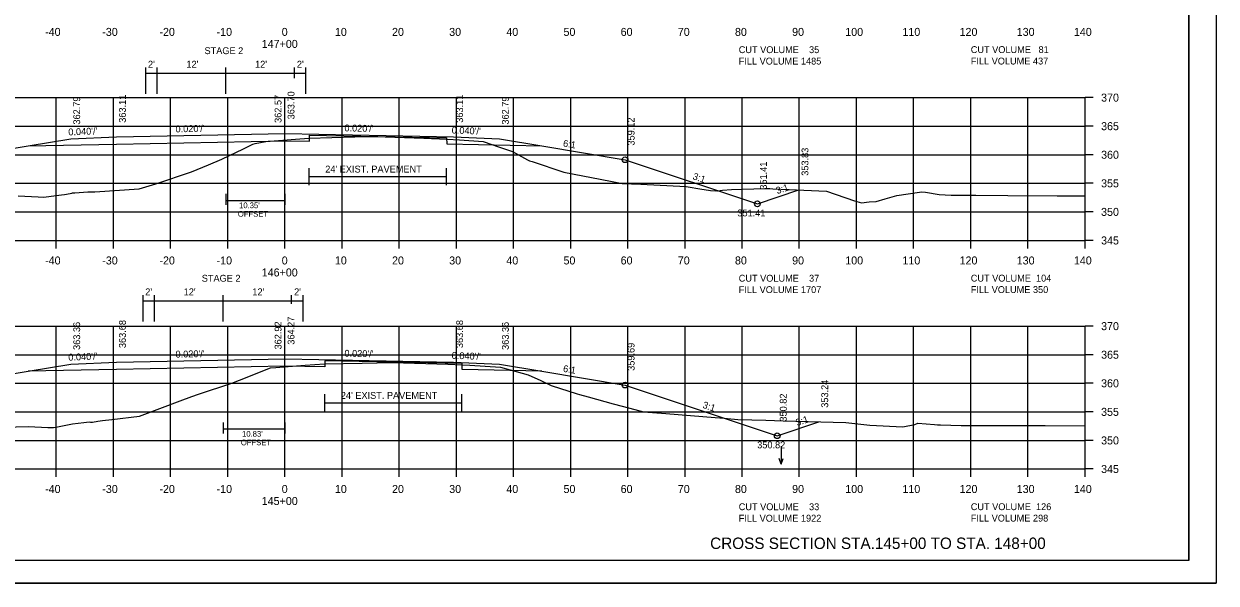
# Model space of a CAD drawing. Extents: x 1374859 to 1376773, y 382242 to 389804.
# Drawn here: x 1376088.9 to 1376297.5, y 386295.2 to 386393.1 of the extents above; entities that cross this region are included whole.
import ezdxf

# ---------------------------------------------------------------- set-up
doc = ezdxf.new("R2010")
doc.units = 0
for name, color, linetype in [('R_Axis', 7, 'Continuous'), ('R_Axis Annot', 7, 'Continuous'), ('R_Border', 7, 'Continuous'), ('R_Border Notes', 7, 'Continuous'), ('R_Draft', 7, 'Continuous'), ('R_Exist Surface', 7, 'Continuous'), ('R_Fin Surface', 7, 'Continuous'), ('R_Grid', 7, 'Continuous'), ('R_MOT', 7, 'Continuous'), ('R_No Plot', 7, 'Continuous'), ('R_Water Annot', 7, 'Continuous'), ('R_Xsect Elev', 7, 'Continuous'), ('R_Xsect Slope', 7, 'Continuous')]:
    doc.layers.add(name, color=color, linetype=linetype)

msp = doc.modelspace()

# ---------------------------------------------------------------- linework, layer by layer
at = {"layer": 'R_Axis'}
for p, q in [((1376274.57, 386355.14), (1376274.57, 386380.14)), ((1376275.97, 386380.14), (1376274.57, 386380.14)), ((1376275.97, 386375.14), (1376274.57, 386375.14)), ((1376275.97, 386370.14), (1376274.57, 386370.14)), ((1376275.97, 386365.14), (1376274.57, 386365.14)), ((1376275.97, 386360.14), (1376274.57, 386360.14)), ((1375994.57, 386355.14), (1376274.57, 386355.14)), ((1376094.57, 386353.74), (1376094.57, 386355.14)), ((1376104.57, 386353.74), (1376104.57, 386355.14)), ((1376114.57, 386353.74), (1376114.57, 386355.14)), ((1376124.57, 386353.74), (1376124.57, 386355.14)), ((1376134.57, 386353.74), (1376134.57, 386355.14)), ((1376144.57, 386353.74), (1376144.57, 386355.14)), ((1376154.57, 386353.74), (1376154.57, 386355.14)), ((1376164.57, 386353.74), (1376164.57, 386355.14)), ((1376174.57, 386353.74), (1376174.57, 386355.14)), ((1376184.57, 386353.74), (1376184.57, 386355.14)), ((1376194.57, 386353.74), (1376194.57, 386355.14)), ((1376204.57, 386353.74), (1376204.57, 386355.14)), ((1376214.57, 386353.74), (1376214.57, 386355.14)), ((1376224.57, 386353.74), (1376224.57, 386355.14)), ((1376234.57, 386353.74), (1376234.57, 386355.14)), ((1376244.57, 386353.74), (1376244.57, 386355.14)), ((1376254.57, 386353.74), (1376254.57, 386355.14)), ((1376264.57, 386353.74), (1376264.57, 386355.14)), ((1376274.57, 386353.74), (1376274.57, 386355.14)), ((1376275.97, 386355.14), (1376274.57, 386355.14)), ((1376274.57, 386315.14), (1376274.57, 386340.14)), ((1376275.97, 386340.14), (1376274.57, 386340.14)), ((1376275.97, 386335.14), (1376274.57, 386335.14)), ((1376275.97, 386330.14), (1376274.57, 386330.14)), ((1376275.97, 386325.14), (1376274.57, 386325.14)), ((1376275.97, 386320.14), (1376274.57, 386320.14)), ((1375994.57, 386315.14), (1376274.57, 386315.14)), ((1376094.57, 386313.74), (1376094.57, 386315.14)), ((1376104.57, 386313.74), (1376104.57, 386315.14)), ((1376114.57, 386313.74), (1376114.57, 386315.14)), ((1376124.57, 386313.74), (1376124.57, 386315.14)), ((1376134.57, 386313.74), (1376134.57, 386315.14)), ((1376144.57, 386313.74), (1376144.57, 386315.14)), ((1376154.57, 386313.74), (1376154.57, 386315.14)), ((1376164.57, 386313.74), (1376164.57, 386315.14)), ((1376174.57, 386313.74), (1376174.57, 386315.14)), ((1376184.57, 386313.74), (1376184.57, 386315.14)), ((1376194.57, 386313.74), (1376194.57, 386315.14)), ((1376204.57, 386313.74), (1376204.57, 386315.14)), ((1376214.57, 386313.74), (1376214.57, 386315.14)), ((1376224.57, 386313.74), (1376224.57, 386315.14)), ((1376234.57, 386313.74), (1376234.57, 386315.14)), ((1376244.57, 386313.74), (1376244.57, 386315.14)), ((1376254.57, 386313.74), (1376254.57, 386315.14)), ((1376264.57, 386313.74), (1376264.57, 386315.14)), ((1376274.57, 386313.74), (1376274.57, 386315.14)), ((1376275.97, 386315.14), (1376274.57, 386315.14))]:
    msp.add_line(p, q, dxfattribs=at)
at = {"layer": 'R_Border'}
for q in [(1376292.75, 386504.6), (1375976.57, 386299.14)]:
    msp.add_line((1376292.75, 386299.14), q, dxfattribs=at)
at = {"layer": 'R_Border Notes'}
for points in [[(1376138.75, 386367.81), (1376138.75, 386364.81)], [(1376162.76, 386367.81), (1376162.76, 386364.81)], [(1376138.75, 386366.31), (1376162.76, 386366.31)], [(1376141.48, 386328.21), (1376141.48, 386325.21)], [(1376165.48, 386328.21), (1376165.48, 386325.21)], [(1376141.48, 386326.71), (1376165.48, 386326.71)]]:
    msp.add_lwpolyline(points, dxfattribs=at)
at = {"layer": 'R_Exist Surface'}
for points in [[(1376087.89, 386362.93), (1376091.4, 386362.75), (1376092.31, 386362.7), (1376092.79, 386362.77), (1376095.49, 386363.15), (1376096.02, 386363.21), (1376096.97, 386363.37), (1376097.27, 386363.41), (1376097.42, 386363.46), (1376097.83, 386363.48), (1376100.06, 386363.63), (1376101.29, 386363.65), (1376109.09, 386364.16), (1376111.97, 386365.07), (1376118.21, 386367.14), (1376121.21, 386368.36), (1376123.51, 386369.35), (1376127.3, 386371.2), (1376128.97, 386372.02), (1376129.34, 386372.09), (1376131.24, 386372.45), (1376136.44, 386372.86), (1376138.75, 386373.03), (1376146.78, 386373.25), (1376150.42, 386373.34), (1376158.87, 386373.03), (1376162.97, 386372.87), (1376165.14, 386372.73), (1376169.24, 386372.45), (1376172.12, 386371.47), (1376174.4, 386370.68), (1376177.04, 386369.26), (1376177.38, 386369.08), (1376177.81, 386368.93), (1376183.39, 386367.07), (1376191.54, 386365.49), (1376193.58, 386365.13), (1376196.86, 386364.98), (1376204.79, 386364.59), (1376207.54, 386364.14), (1376208.7, 386363.95), (1376209.02, 386363.9), (1376209.89, 386363.84), (1376210.06, 386363.86), (1376210.14, 386363.85), (1376210.28, 386363.83), (1376211.14, 386363.93), (1376212.7, 386364.05), (1376218.54, 386364.21), (1376219.41, 386364.23), (1376219.94, 386364.2), (1376222.8, 386364.04), (1376225.36, 386363.95), (1376229.32, 386363.77), (1376234.25, 386362.09), (1376235.46, 386361.72), (1376236.8, 386361.91), (1376237.99, 386361.98), (1376239.58, 386362.43), (1376241.63, 386363.03), (1376245.57, 386363.58), (1376246.03, 386363.64), (1376246.62, 386363.59), (1376249.05, 386363.16), (1376251.13, 386363.04), (1376254.11, 386363.06), (1376255.43, 386363.08), (1376261.04, 386363.03), (1376269.69, 386362.93), (1376274.57, 386362.94)], [(1376083.22, 386322.42), (1376089.68, 386322.58), (1376093.09, 386322.42), (1376094.05, 386322.4), (1376094.47, 386322.49), (1376097.4, 386323.07), (1376099.37, 386323.27), (1376100.32, 386323.37), (1376100.55, 386323.36), (1376100.91, 386323.36), (1376101.85, 386323.52), (1376102.63, 386323.65), (1376104.29, 386323.83), (1376109.1, 386324.38), (1376116.22, 386327.06), (1376118.28, 386327.81), (1376119.45, 386328.21), (1376125.3, 386330.16), (1376126.6, 386330.67), (1376132.04, 386332.84), (1376133, 386332.92), (1376134.36, 386333.04), (1376138.09, 386333.3), (1376141.48, 386333.53), (1376148.07, 386333.68), (1376153.37, 386333.8), (1376163.07, 386333.46), (1376165.59, 386333.38), (1376166.93, 386333.31), (1376172.26, 386332.95), (1376173.99, 386332.49), (1376177.14, 386331.61), (1376179.32, 386330.65), (1376181.15, 386329.75), (1376185.72, 386328.32), (1376186.12, 386328.19), (1376187.6, 386327.77), (1376192.01, 386326.52), (1376194.9, 386325.78), (1376197.3, 386325.17), (1376201.23, 386324.85), (1376209.87, 386324.14), (1376211.4, 386324.01), (1376213.83, 386323.83), (1376218.7, 386323.67), (1376221.75, 386323.56), (1376232.73, 386323.25), (1376236.93, 386322.83), (1376242.69, 386322.51), (1376244.77, 386322.93), (1376245.33, 386323.15), (1376248.2, 386322.91), (1376248.74, 386322.87), (1376249.26, 386322.85), (1376252.89, 386322.74), (1376259.75, 386322.76), (1376264.43, 386322.76), (1376267.57, 386322.74), (1376274.57, 386322.69)]]:
    msp.add_lwpolyline(points, dxfattribs=at)
at = {"layer": 'R_Fin Surface'}
for points in [[(1376045, 386362.59), (1376050.02, 386360.91), (1376075.09, 386369.27), (1376089.65, 386371.7), (1376097.09, 386372.93), (1376105.09, 386373.25), (1376134.59, 386373.84), (1376164.09, 386373.25), (1376172.09, 386372.93), (1376179.51, 386371.7), (1376194.09, 386369.27), (1376217.23, 386361.55), (1376224.5, 386363.98)], [(1376089.65, 386371.7), (1376105.1, 386372), (1376134.58, 386372.59)], [(1376134.58, 386372.59), (1376138.85, 386372.51), (1376138.86, 386373.59), (1376162.86, 386373.11), (1376162.87, 386372.03), (1376179.51, 386371.7)], [(1376042.49, 386322.47), (1376047.74, 386320.72), (1376075.09, 386329.83), (1376089.65, 386332.26), (1376097.09, 386333.5), (1376105.09, 386333.82), (1376134.59, 386334.41), (1376164.09, 386333.82), (1376172.09, 386333.5), (1376179.51, 386332.26), (1376194.09, 386329.83), (1376220.7, 386320.96), (1376227.96, 386323.38)], [(1376134.58, 386333.16), (1376105.1, 386332.57), (1376089.65, 386332.26)], [(1376179.51, 386332.26), (1376165.59, 386332.54), (1376165.58, 386333.62), (1376141.58, 386334.1), (1376141.57, 386333.02), (1376134.58, 386333.16)]]:
    msp.add_lwpolyline(points, dxfattribs=at)
at = {"layer": 'R_Grid'}
for p, q in [((1375994.57, 386380.14), (1376274.57, 386380.14)), ((1376094.57, 386355.14), (1376094.57, 386380.14)), ((1376104.57, 386355.14), (1376104.57, 386380.14)), ((1376114.57, 386355.14), (1376114.57, 386380.14)), ((1376124.57, 386355.14), (1376124.57, 386380.14)), ((1376134.57, 386355.14), (1376134.57, 386380.14)), ((1376144.57, 386355.14), (1376144.57, 386380.14)), ((1376154.57, 386355.14), (1376154.57, 386380.14)), ((1376164.57, 386355.14), (1376164.57, 386380.14)), ((1376174.57, 386355.14), (1376174.57, 386380.14)), ((1376184.57, 386355.14), (1376184.57, 386380.14)), ((1376194.57, 386355.14), (1376194.57, 386380.14)), ((1376204.57, 386355.14), (1376204.57, 386380.14)), ((1376214.57, 386355.14), (1376214.57, 386380.14)), ((1376224.57, 386355.14), (1376224.57, 386380.14)), ((1376234.57, 386355.14), (1376234.57, 386380.14)), ((1376244.57, 386355.14), (1376244.57, 386380.14)), ((1376254.57, 386355.14), (1376254.57, 386380.14)), ((1376264.57, 386355.14), (1376264.57, 386380.14)), ((1376274.57, 386355.14), (1376274.57, 386380.14)), ((1375994.57, 386375.14), (1376274.57, 386375.14)), ((1375994.57, 386370.14), (1376274.57, 386370.14)), ((1375994.57, 386365.14), (1376274.57, 386365.14)), ((1375994.57, 386360.14), (1376274.57, 386360.14)), ((1375994.57, 386355.14), (1376274.57, 386355.14)), ((1375994.57, 386340.14), (1376274.57, 386340.14)), ((1376094.57, 386315.14), (1376094.57, 386340.14)), ((1376104.57, 386315.14), (1376104.57, 386340.14)), ((1376114.57, 386315.14), (1376114.57, 386340.14)), ((1376124.57, 386315.14), (1376124.57, 386340.14)), ((1376134.57, 386315.14), (1376134.57, 386340.14)), ((1376144.57, 386315.14), (1376144.57, 386340.14)), ((1376154.57, 386315.14), (1376154.57, 386340.14)), ((1376164.57, 386315.14), (1376164.57, 386340.14)), ((1376174.57, 386315.14), (1376174.57, 386340.14)), ((1376184.57, 386315.14), (1376184.57, 386340.14)), ((1376194.57, 386315.14), (1376194.57, 386340.14)), ((1376204.57, 386315.14), (1376204.57, 386340.14)), ((1376214.57, 386315.14), (1376214.57, 386340.14)), ((1376224.57, 386315.14), (1376224.57, 386340.14)), ((1376234.57, 386315.14), (1376234.57, 386340.14)), ((1376244.57, 386315.14), (1376244.57, 386340.14)), ((1376254.57, 386315.14), (1376254.57, 386340.14)), ((1376264.57, 386315.14), (1376264.57, 386340.14)), ((1376274.57, 386315.14), (1376274.57, 386340.14)), ((1375994.57, 386335.14), (1376274.57, 386335.14)), ((1375994.57, 386330.14), (1376274.57, 386330.14)), ((1375994.57, 386325.14), (1376274.57, 386325.14)), ((1375994.57, 386320.14), (1376274.57, 386320.14)), ((1375994.57, 386315.14), (1376274.57, 386315.14))]:
    msp.add_line(p, q, dxfattribs=at)
at = {"layer": 'R_MOT'}
for p, q in [((1376110.22, 386380.79), (1376110.22, 386385.43)), ((1376110.22, 386384.43), (1376138.22, 386384.43)), ((1376112.22, 386380.79), (1376112.22, 386385.43)), ((1376124.22, 386380.79), (1376124.22, 386385.43)), ((1376136.22, 386383.54), (1376136.22, 386385.43)), ((1376138.22, 386380.79), (1376138.22, 386385.43)), ((1376124.22, 386363.28), (1376124.22, 386361.35)), ((1376134.57, 386362.1), (1376124.22, 386362.1)), ((1376134.57, 386363.28), (1376134.57, 386361.35)), ((1376109.74, 386340.95), (1376109.74, 386345.59)), ((1376111.74, 386340.95), (1376111.74, 386345.59)), ((1376123.74, 386340.95), (1376123.74, 386345.59)), ((1376135.74, 386344.07), (1376135.74, 386345.59)), ((1376137.74, 386340.95), (1376137.74, 386345.59)), ((1376109.74, 386344.59), (1376137.74, 386344.59)), ((1376123.74, 386323.28), (1376123.74, 386321.35)), ((1376134.57, 386322.1), (1376123.74, 386322.1)), ((1376134.57, 386323.28), (1376134.57, 386321.35))]:
    msp.add_line(p, q, dxfattribs=at)
at = {"layer": 'R_No Plot'}
msp.add_line((1375964.17, 386295.16), (1376297.5, 386295.16), dxfattribs=at)
for points in [[(1375964.16, 386508.5), (1376297.5, 386508.5), (1376297.5, 386295.16), (1375964.16, 386295.16)], [(1376210.49, 386504.6), (1376210.49, 386494.72), (1376246.22, 386494.72), (1376246.22, 386491.8), (1376269.42, 386491.8), (1376269.42, 386467.47), (1376292.75, 386467.47), (1376292.75, 386299.14), (1375976.57, 386299.14), (1375976.57, 386504.6)]]:
    msp.add_lwpolyline(points, close=True, dxfattribs=at)
for centre in [(1376194.09, 386369.27), (1376217.23, 386361.55), (1376194.09, 386329.83), (1376220.7, 386320.96)]:
    msp.add_circle(centre, 0.5, dxfattribs=at)
at = {"layer": 'R_Water Annot'}
for p, q in [((1376221.41, 386319.15), (1376221.41, 386316.01)), ((1376221.41, 386316.01), (1376221.06, 386316.97)), ((1376221.41, 386316.01), (1376221.76, 386316.97))]:
    msp.add_line(p, q, dxfattribs=at)

# ---------------------------------------------------------------- texts
at = {"layer": 'R_Axis Annot'}
for s, height, p in [('-40', 1.4, (1376092.61, 386390.94)), ('-30', 1.4, (1376102.61, 386390.94)), ('-20', 1.4, (1376112.61, 386390.94)), ('-10', 1.4, (1376122.61, 386390.94)), ('0', 1.4, (1376134.01, 386390.94)), ('10', 1.4, (1376143.31, 386390.94)), ('20', 1.4, (1376153.31, 386390.94)), ('30', 1.4, (1376163.31, 386390.94)), ('40', 1.4, (1376173.31, 386390.94)), ('50', 1.4, (1376183.31, 386390.94)), ('60', 1.4, (1376193.31, 386390.94)), ('70', 1.4, (1376203.31, 386390.94)), ('80', 1.4, (1376213.31, 386390.94)), ('90', 1.4, (1376223.31, 386390.94)), ('100', 1.4, (1376232.61, 386390.94)), ('110', 1.4, (1376242.61, 386390.94)), ('120', 1.4, (1376252.61, 386390.94)), ('130', 1.4, (1376262.61, 386390.94)), ('140', 1.4, (1376272.61, 386390.94)), ('147+00', 1.4, (1376130.51, 386388.84)), ('CUT VOLUME    35', 1.2, (1376213.97, 386387.93)), ('CUT VOLUME   81', 1.2, (1376254.57, 386387.94)), ('FILL VOLUME 1485', 1.2, (1376213.97, 386385.93)), ('FILL VOLUME 437', 1.2, (1376254.57, 386385.94)), ('370', 1.4, (1376277.37, 386379.44)), ('365', 1.4, (1376277.37, 386374.44)), ('360', 1.4, (1376277.37, 386369.44)), ('355', 1.4, (1376277.37, 386364.44)), ('350', 1.4, (1376277.37, 386359.44)), ('345', 1.4, (1376277.37, 386354.44)), ('-40', 1.4, (1376092.61, 386350.94)), ('-30', 1.4, (1376102.61, 386350.94)), ('-20', 1.4, (1376112.61, 386350.94)), ('-10', 1.4, (1376122.61, 386350.94)), ('0', 1.4, (1376134.01, 386350.94)), ('10', 1.4, (1376143.31, 386350.94)), ('20', 1.4, (1376153.31, 386350.94)), ('30', 1.4, (1376163.31, 386350.94)), ('40', 1.4, (1376173.31, 386350.94)), ('50', 1.4, (1376183.31, 386350.94)), ('60', 1.4, (1376193.31, 386350.94)), ('70', 1.4, (1376203.31, 386350.94)), ('80', 1.4, (1376213.31, 386350.94)), ('90', 1.4, (1376223.31, 386350.94)), ('100', 1.4, (1376232.61, 386350.94)), ('110', 1.4, (1376242.61, 386350.94)), ('120', 1.4, (1376252.61, 386350.94)), ('130', 1.4, (1376262.61, 386350.94)), ('140', 1.4, (1376272.61, 386350.94)), ('146+00', 1.4, (1376130.51, 386348.84)), ('CUT VOLUME    37', 1.2, (1376213.97, 386347.93)), ('CUT VOLUME  104', 1.2, (1376254.57, 386347.94)), ('FILL VOLUME 1707', 1.2, (1376213.97, 386345.93)), ('FILL VOLUME 350', 1.2, (1376254.57, 386345.94)), ('370', 1.4, (1376277.37, 386339.44)), ('365', 1.4, (1376277.37, 386334.44)), ('360', 1.4, (1376277.37, 386329.44)), ('355', 1.4, (1376277.37, 386324.44)), ('350', 1.4, (1376277.37, 386319.44)), ('345', 1.4, (1376277.37, 386314.44)), ('-40', 1.4, (1376092.61, 386310.94)), ('-30', 1.4, (1376102.61, 386310.94)), ('-20', 1.4, (1376112.61, 386310.94)), ('-10', 1.4, (1376122.61, 386310.94)), ('0', 1.4, (1376134.01, 386310.94)), ('10', 1.4, (1376143.31, 386310.94)), ('20', 1.4, (1376153.31, 386310.94)), ('30', 1.4, (1376163.31, 386310.94)), ('40', 1.4, (1376173.31, 386310.94)), ('50', 1.4, (1376183.31, 386310.94)), ('60', 1.4, (1376193.31, 386310.94)), ('70', 1.4, (1376203.31, 386310.94)), ('80', 1.4, (1376213.31, 386310.94)), ('90', 1.4, (1376223.31, 386310.94)), ('100', 1.4, (1376232.61, 386310.94)), ('110', 1.4, (1376242.61, 386310.94)), ('120', 1.4, (1376252.61, 386310.94)), ('130', 1.4, (1376262.61, 386310.94)), ('140', 1.4, (1376272.61, 386310.94)), ('145+00', 1.4, (1376130.51, 386308.84)), ('CUT VOLUME    33', 1.2, (1376213.97, 386307.93)), ('CUT VOLUME  126', 1.2, (1376254.57, 386307.94)), ('FILL VOLUME 1922', 1.2, (1376213.97, 386305.93)), ('FILL VOLUME 298', 1.2, (1376254.57, 386305.94))]:
    msp.add_text(s, height=height, dxfattribs=at).set_placement(p)
at = {"layer": 'R_Border Notes'}
for p in [(1376141.62, 386367.03), (1376144.35, 386327.42)]:
    msp.add_text("24' EXIST. PAVEMENT", height=1.2, rotation=0, dxfattribs=at).set_placement(p)
at = {"layer": 'R_Draft'}
for s, height, p in [("10.35'", 1, (1376126.55, 386360.79)), ('OFFSET', 1, (1376126.34, 386359.29)), ("10.83'", 1, (1376127.07, 386320.79)), ('OFFSET', 1, (1376126.86, 386319.29)), ('CROSS SECTION STA.145+00 TO STA. 148+00', 2, (1376208.97, 386301.14))]:
    msp.add_text(s, height=height, dxfattribs=at).set_placement(p)
at = {"layer": 'R_MOT'}
for p in [(1376120.5, 386387.75), (1376120.02, 386347.92)]:
    msp.add_text('STAGE 2', height=1.2, rotation=0, dxfattribs=at).set_placement(p)
for s, p in [("2'", (1376110.61, 386385.38)), ("12'", (1376117.34, 386385.38)), ("12'", (1376129.35, 386385.38)), ("2'", (1376136.66, 386385.38)), ("2'", (1376110.13, 386345.55)), ("12'", (1376116.86, 386345.55)), ("12'", (1376128.87, 386345.55)), ("2'", (1376136.18, 386345.55))]:
    msp.add_text(s, height=1.2, dxfattribs=at).set_placement(p)
at = {"layer": 'R_Xsect Elev'}
for s, p in [('362.79', (1376098.74, 386375.42)), ('363.11', (1376106.74, 386375.74)), ('362.57', (1376133.97, 386375.71)), ('363.70', (1376136.24, 386376.33)), ('363.11', (1376165.74, 386375.74)), ('362.79', (1376173.74, 386375.42)), ('359.12', (1376195.74, 386371.75)), ('353.83', (1376226.16, 386366.46)), ('351.41', (1376218.89, 386364.03)), ('363.36', (1376098.74, 386335.98)), ('363.68', (1376106.74, 386336.3)), ('362.92', (1376133.97, 386336.06)), ('364.27', (1376136.24, 386336.89)), ('363.68', (1376165.74, 386336.3)), ('363.36', (1376173.74, 386335.98)), ('359.69', (1376195.74, 386332.32)), ('353.24', (1376229.62, 386325.86)), ('350.82', (1376222.36, 386323.44))]:
    msp.add_text(s, height=1.2, rotation=90, dxfattribs=at).set_placement(p)
for s, p in [('351.41', (1376213.73, 386359.35)), ('350.82', (1376217.2, 386318.76))]:
    msp.add_text(s, height=1.2, dxfattribs=at).set_placement(p)
at = {"layer": 'R_Xsect Slope'}
for s, rotation, p in [("0.040'/'", 2.2906, (1376096.69, 386373.52)), ("0.020'/'", 1.1458, (1376115.44, 386374.06)), ("0.020'/'", 358.8542, (1376144.97, 386374.24)), ("0.040'/'", 357.7094, (1376163.73, 386373.87)), ('6:1', 350.5358, (1376183.17, 386371.59)), ('3:1', 341.5651, (1376205.82, 386365.88)), ('3:1', 18.4349, (1376220.71, 386363.24)), ("0.040'/'", 2.2906, (1376096.69, 386334.09)), ("0.020'/'", 1.1458, (1376115.44, 386334.63)), ("0.020'/'", 358.8542, (1376144.97, 386334.8)), ("0.040'/'", 357.7094, (1376163.73, 386334.44)), ('6:1', 350.5358, (1376183.17, 386332.16)), ('3:1', 341.5651, (1376207.55, 386325.87)), ('3:1', 18.4349, (1376224.18, 386322.65))]:
    msp.add_text(s, height=1.2, rotation=rotation, dxfattribs=at).set_placement(p)

doc.saveas('drawing.dxf')
